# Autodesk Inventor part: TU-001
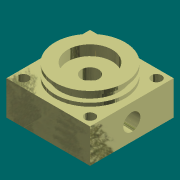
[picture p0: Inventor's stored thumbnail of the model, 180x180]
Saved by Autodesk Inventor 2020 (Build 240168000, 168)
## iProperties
Created: 2008-05
Part Number: TU-001
Document SubType Name: Modeling
Designer: PN
Density: 7.86 g/cm^3
Material: Steel, Mild
Description: Cylinder Head Cover_Back
Mass: 383.317 g
Surface Area: 134.207 cm^2
Volume: 48.7681 cm^3
Appearance: Nickel
d32: 6.000 mm
Author: PN
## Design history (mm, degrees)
sketch "Sketch1"
  geometry: L1 (-24.5, 24.5)-(24.5, 24.5); L2 (24.5, 24.5)-(24.5, -24.5); L3 (24.5, -24.5)-(-24.5, -24.5); L4 (-24.5, -24.5)-(-24.5, 24.5); 3 further points
  constraints: 8 end point, 2 midpoint, 2 parallel, 1 horizontal, 1 horizontal alignment, 1 perpendicular, 1 vertical alignment
  dimensions: "Width" = 49 distance of L1.start L1.end; "Height" = 49 distance of L3.end L1.start (= Width)
extrude "Extrusion1" new body sketch "Sketch1" distance "d2" = 20; taper "d3" = 0 deg
sketch "Sketch2"
  geometry: L1 (24.5, 24.5)-(24.5, -24.5) reference; L2 (-24.5, 24.5)-(24.5, 24.5) reference; L3 (-24.5, -24.5)-(-24.5, 24.5) reference; L4 (24.5, -24.5)-(-24.5, -24.5) reference; L5 (19.5, 19.5)-(19.5, -19.5); L6 (19.5, -19.5)-(-19.5, -19.5); L7 (-19.5, -19.5)-(-19.5, 19.5); L8 (-19.5, 19.5)-(19.5, 19.5); 1 further point
  constraints: 8 end point, 3 other
  dimensions: "d4" = 5 distance between parallel lines of L7 L3; "d5" = 39 distance of L5.end L6.end (derived); "d6" = 39 distance of L6.end L7.end (derived)
hole "Hole1" sketch "Sketch2" at (-19.5, -19.5) diameter "d7" = 6; stored, may be unused: countersink angle "d11" = 90 deg, drill point angle "d13" = 118 deg; dims "d8" = 6, "d9" = 4, "d10" = 2, "d12" = 8
pattern_linear "Rectangular Pattern1" dims "d16" = 39 (= d5), "d19" = 39 (= d6)
sketch "Sketch3"
  geometry: L1 (-24.5, 20)-(24.5, 20) reference; L2 (0, 20)-(0, 28); L3 (0, 28)-(20.5, 28); L4 (20.5, 28)-(20.5, 26); L5 (20.5, 26)-(17.5, 26); L6 (17.5, 26)-(17.5, 22); L7 (17.5, 22)-(20.5, 22); L8 (20.5, 22)-(20.5, 20); 1 further point
  constraints: 14 end point, 4 perpendicular, 2 collinear, 2 parallel, 1 midpoint, 1 point on line
  dimensions: "d25" = 8 distance of L2.start L2.end; "d26" = 20.5 distance of L2.end L3.end; "d27" = 2 distance of L3.end L4.end; "d28" = 4 distance of L5.end L6.end; "d29" = 17.5 distance between parallel lines of L6 L2
revolve "Revolution1" sketch "Sketch3" stored, may be unused: angle "d30" = 90 deg
sketch "Sketch4"
  geometry: L1 (0, -20)-(49, -20) reference; L2 (0, 0)-(0, -20) reference; L3 (24.5, -20)-(24.5, -14); 1 further point
  constraints: 2 end point, 1 midpoint, 1 parallel
  dimensions: "d32" = 6 distance of L3.start L3.end
hole "Hole2" diameter "d35" = 10; stored, may be unused: countersink angle "d39" = 90 deg, drill point angle "d41" = 0 deg; dims "d33" = 10, "d34" = 10, "d36" = 6, "d37" = 26, "d38" = 6, "d40" = 18
hole "Hole3" sketch "Sketch4" diameter "d42" = 4.134; stored, may be unused: countersink angle "d46" = 90 deg, drill point angle "d48" = 118 deg; dims "d43" = 6, "d44" = 26, "d45" = 6, "d47" = 18
sketch "Sketch6"
  geometry: L1 (0, 49)-(0, 0) reference; L2 (0, 49)-(-20, 49) reference; 4 further points
  constraints: 2 midpoint, 1 horizontal alignment, 1 vertical alignment
hole "Hole4" sketch "Sketch6" at (-10, 24.5) diameter "d49" = 10; stored, may be unused: countersink angle "d53" = 90 deg, drill point angle "d55" = 118 deg; dims "d50" = 6, "d51" = 26, "d52" = 6, "d54" = 10
mirror "Mirror1"
body "Solid1"
